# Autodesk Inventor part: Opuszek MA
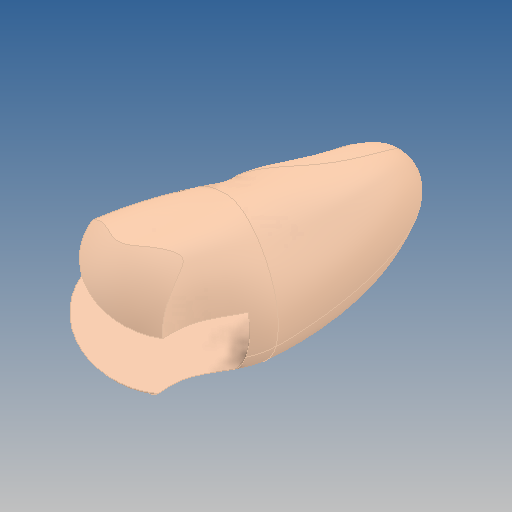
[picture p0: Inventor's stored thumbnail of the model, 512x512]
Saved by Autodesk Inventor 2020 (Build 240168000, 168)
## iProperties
Created: 2019-10
Part Number: Opuszek MA
Material: GFRP
Document SubType Name: Modeling
Designer: yello
Density: 1.75 g/cm^3
Appearance: Default
Author: yello
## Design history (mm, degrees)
feature "Opuszek MA"
body "Solid1"
